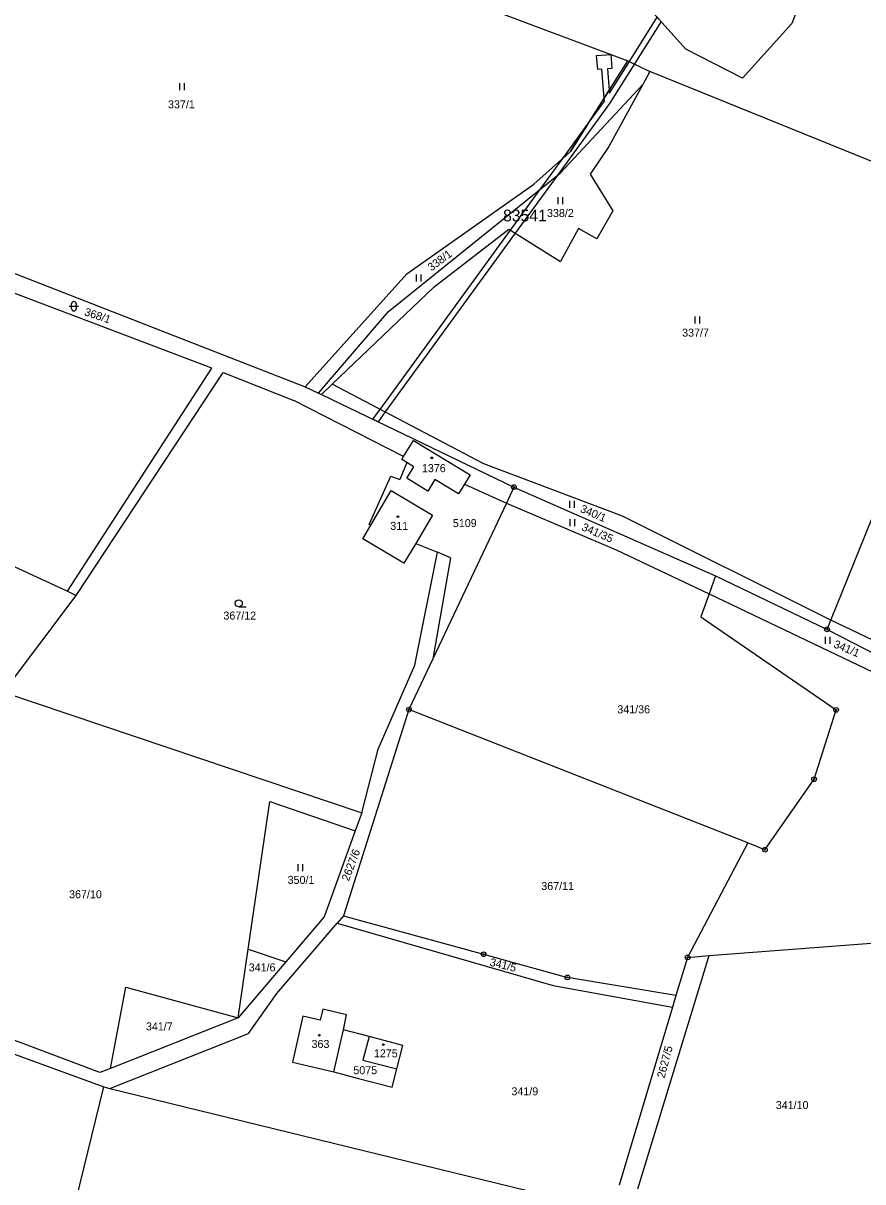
# Model space of a CAD drawing. Extents: x -439246 to -433691, y -1130252 to -1121148.
# Drawn here: x -436804.9 to -436626.4, y -1124037.6 to -1123791.4 of the extents above; entities that cross this region are included whole.
import ezdxf

# ---------------------------------------------------------------- set-up
doc = ezdxf.new("R2010")
doc.units = 0
for name, color, linetype in [('Vrstva 1', 7, 'Continuous'), ('Vrstva 18', 7, 'Continuous'), ('Vrstva 19', 7, 'Continuous'), ('Vrstva 24', 7, 'Continuous'), ('Vrstva 25', 7, 'Continuous'), ('Vrstva 3', 7, 'Continuous'), ('Vrstva 30', 7, 'Continuous'), ('Vrstva 37', 7, 'Continuous'), ('Vrstva 53', 7, 'Continuous'), ('Vrstva 6', 7, 'Continuous')]:
    doc.layers.add(name, color=color, linetype=linetype)

msp = doc.modelspace()

# ---------------------------------------------------------------- linework, layer by layer
at = {"layer": 'Vrstva 1'}
for p, q in [((-436724.05, -1123883.47), (-436747.33, -1123871.55)), ((-436724.05, -1123883.47), (-436721.94, -1123880.01)), ((-436721.94, -1123880.01), (-436709.84, -1123887.31)), ((-436723.36, -1123884.73), (-436724.84, -1123888.36)), ((-436724.43, -1123884.09), (-436724.05, -1123883.47)), ((-436723.36, -1123884.73), (-436724.43, -1123884.09)), ((-436721.86, -1123885.63), (-436723.36, -1123884.73)), ((-436723.35, -1123888.07), (-436721.86, -1123885.63)), ((-436709.84, -1123887.31), (-436711.08, -1123889.35)), ((-436718.89, -1123890.78), (-436723.35, -1123888.07)), ((-436717.37, -1123888.34), (-436718.89, -1123890.78)), ((-436712.33, -1123891.4), (-436717.37, -1123888.34)), ((-436711.08, -1123889.35), (-436712.33, -1123891.4)), ((-436711.08, -1123889.35), (-436702.18, -1123893.33)), ((-436730.97, -1123898.04), (-436726.63, -1123890.68)), ((-436726.63, -1123890.68), (-436717.86, -1123895.93)), ((-436717.86, -1123895.93), (-436721.44, -1123901.9)), ((-436732.66, -1123900.9), (-436730.97, -1123898.04)), ((-436730.97, -1123898.04), (-436731.36, -1123897.88)), ((-436723.95, -1123906.09), (-436732.66, -1123900.9)), ((-436721.44, -1123901.9), (-436723.95, -1123906.09)), ((-436721.44, -1123901.9), (-436716.79, -1123903.78)), ((-436650.87, -1123965.56), (-436722.89, -1123937.23)), ((-436650.87, -1123965.56), (-436663.68, -1123989.86)), ((-436647.23, -1123966.99), (-436650.87, -1123965.56)), ((-436659.11, -1123989.5), (-436618.57, -1123986.35)), ((-436674.24, -1124039.06), (-436659.11, -1123989.5)), ((-436663.68, -1123989.86), (-436666.13, -1123997.99)), ((-436663.68, -1123989.86), (-436659.11, -1123989.5)), ((-436692.21, -1123995.85), (-436666.86, -1124000.45)), ((-436666.13, -1123997.99), (-436689.19, -1123994.12)), ((-436666.13, -1123997.99), (-436666.86, -1124000.45)), ((-436666.86, -1124000.45), (-436678.21, -1124038.28))]:
    msp.add_line(p, q, dxfattribs=at)
for points in [[(-436688.54, -1123818.64), (-436676.38, -1123799.34)], [(-436676.38, -1123799.34), (-436671.7, -1123801.64)], [(-436671.7, -1123801.64), (-436673.19, -1123804.38)], [(-436690.77, -1123823.21), (-436673.19, -1123804.38)], [(-436673.19, -1123804.38), (-436680.39, -1123817.59)], [(-436680.39, -1123817.59), (-436684.36, -1123823.43)], [(-436696.33, -1123825.6), (-436688.54, -1123818.64)], [(-436727.25, -1123852.66), (-436690.77, -1123823.21)], [(-436684.36, -1123823.43), (-436679.57, -1123831.25)], [(-436723.32, -1123844.66), (-436696.33, -1123825.6)], [(-436679.57, -1123831.25), (-436682.92, -1123837.22)], [(-436717.51, -1123847.42), (-436701.65, -1123835.14)], [(-436701.65, -1123835.14), (-436690.65, -1123841.99)], [(-436686.88, -1123834.99), (-436690.65, -1123841.99)], [(-436682.92, -1123837.22), (-436686.88, -1123834.99)], [(-436822.9, -1123838.25), (-436744.96, -1123868.62)], [(-436764.81, -1123864.68), (-436825.31, -1123841.7)], [(-436744.96, -1123868.62), (-436723.32, -1123844.66)], [(-436739.17, -1123868.08), (-436717.51, -1123847.42)], [(-436742.08, -1123870.01), (-436727.25, -1123852.66)], [(-436795.47, -1123912.07), (-436764.81, -1123864.68)], [(-436793.64, -1123912.95), (-436762.35, -1123865.57)], [(-436762.35, -1123865.57), (-436747.33, -1123871.55)], [(-436633.21, -1123918.19), (-436612.33, -1123866.59)], [(-436744.96, -1123868.62), (-436742.08, -1123870.01)], [(-436742.08, -1123870.01), (-436741.49, -1123870.29)], [(-436739.17, -1123868.08), (-436741.49, -1123870.29)], [(-436741.49, -1123870.29), (-436700.57, -1123889.93)], [(-436706.99, -1123884.97), (-436739.17, -1123868.08)], [(-436677.53, -1123896.15), (-436706.99, -1123884.97)], [(-436846.24, -1123888.58), (-436795.47, -1123912.07)], [(-436731.36, -1123897.88), (-436726.71, -1123887.63)], [(-436726.71, -1123887.63), (-436724.84, -1123888.36)], [(-436700.57, -1123889.93), (-436702.18, -1123893.33)], [(-436700.57, -1123889.93), (-436657.71, -1123908.78)], [(-436702.18, -1123893.33), (-436717.78, -1123926.4)], [(-436702.18, -1123893.33), (-436678.86, -1123903.3)], [(-436633.21, -1123918.19), (-436677.53, -1123896.15)], [(-436721.66, -1123927.8), (-436716.79, -1123903.78)], [(-436714.02, -1123904.96), (-436716.79, -1123903.78)], [(-436678.86, -1123903.3), (-436659.1, -1123912.65)], [(-436714.02, -1123904.96), (-436717.78, -1123926.4)], [(-436657.71, -1123908.78), (-436659.1, -1123912.65)], [(-436657.71, -1123908.78), (-436634.02, -1123920.19)], [(-436795.47, -1123912.07), (-436793.64, -1123912.95)], [(-436809.03, -1123933.53), (-436793.64, -1123912.95)], [(-436659.1, -1123912.65), (-436660.85, -1123917.53)], [(-436659.1, -1123912.65), (-436624.26, -1123929.23)], [(-436660.85, -1123917.53), (-436632.1, -1123937.28)], [(-436634.02, -1123920.19), (-436633.21, -1123918.19)], [(-436612.08, -1123928.3), (-436633.21, -1123918.19)], [(-436634.02, -1123920.19), (-436571.37, -1123952.32)], [(-436717.78, -1123926.4), (-436722.89, -1123937.23)], [(-436729.44, -1123945.64), (-436721.66, -1123927.8)], [(-436809.03, -1123933.53), (-436732.89, -1123959.16)], [(-436722.89, -1123937.23), (-436736.79, -1123981.01)], [(-436636.78, -1123952.03), (-436632.1, -1123937.28)], [(-436732.89, -1123959.16), (-436729.44, -1123945.64)], [(-436647.23, -1123966.99), (-436636.78, -1123952.03)], [(-436757.02, -1123988.12), (-436752.43, -1123956.77)], [(-436752.43, -1123956.77), (-436734.28, -1123962.99)], [(-436732.89, -1123959.16), (-436734.28, -1123962.99)], [(-436734.28, -1123962.99), (-436740.88, -1123981.25)], [(-436736.79, -1123981.01), (-436738.17, -1123982.61)], [(-436736.79, -1123981.01), (-436707.01, -1123989.21)], [(-436750.95, -1123997.55), (-436738.17, -1123982.61)], [(-436740.88, -1123981.25), (-436749.03, -1123990.8)], [(-436738.17, -1123982.61), (-436692.21, -1123995.85)], [(-436759.15, -1124002.68), (-436757.02, -1123988.12)], [(-436757.02, -1123988.12), (-436749.03, -1123990.8)], [(-436749.03, -1123990.8), (-436759.15, -1124002.68)], [(-436707.01, -1123989.21), (-436689.19, -1123994.12)], [(-436788.55, -1124014.36), (-436832.84, -1123997.68)], [(-436786.3, -1124013.47), (-436783.06, -1123996.21)], [(-436783.06, -1123996.21), (-436759.15, -1124002.68)], [(-436757, -1124006.03), (-436750.95, -1123997.55)], [(-436833.34, -1124000.72), (-436787.74, -1124017.4)], [(-436759.15, -1124002.68), (-436786.3, -1124013.47)], [(-436745.4, -1124002.39), (-436747.6, -1124012.1)], [(-436741.77, -1124003.2), (-436745.4, -1124002.39)], [(-436741.17, -1124000.89), (-436741.77, -1124003.2)], [(-436736.12, -1124002.04), (-436741.17, -1124000.89)], [(-436736.81, -1124005.28), (-436736.12, -1124002.04)], [(-436738.84, -1124014.16), (-436736.81, -1124005.28)], [(-436731.37, -1124006.69), (-436736.81, -1124005.28)], [(-436786.48, -1124017.71), (-436757, -1124006.03)], [(-436731.37, -1124006.69), (-436732.65, -1124011.68)], [(-436724.16, -1124008.56), (-436731.37, -1124006.69)], [(-436725.43, -1124013.54), (-436724.16, -1124008.56)], [(-436747.6, -1124012.1), (-436738.84, -1124014.16)], [(-436732.65, -1124011.68), (-436725.43, -1124013.54)], [(-436786.3, -1124013.47), (-436788.55, -1124014.36)], [(-436738.84, -1124014.16), (-436733.64, -1124015.61)], [(-436726.42, -1124017.44), (-436725.43, -1124013.54)], [(-436797.92, -1124059.04), (-436787.74, -1124017.4)], [(-436787.74, -1124017.4), (-436786.48, -1124017.71)], [(-436786.48, -1124017.71), (-436678.89, -1124043.98)], [(-436733.64, -1124015.61), (-436726.42, -1124017.44)]]:
    msp.add_lwpolyline(points, dxfattribs=at)
at = {"layer": 'Vrstva 24'}
for centre, radius in [((-436700.57, -1123889.93), 0.5), ((-436700.57, -1123889.93), 0.1), ((-436634.02, -1123920.19), 0.5), ((-436634.02, -1123920.19), 0.1), ((-436722.89, -1123937.23), 0.5), ((-436632.1, -1123937.28), 0.5), ((-436722.89, -1123937.23), 0.1), ((-436632.1, -1123937.28), 0.1), ((-436636.78, -1123952.03), 0.5), ((-436636.78, -1123952.03), 0.1), ((-436647.23, -1123966.99), 0.5), ((-436647.23, -1123966.99), 0.1), ((-436707.01, -1123989.21), 0.5), ((-436707.01, -1123989.21), 0.1), ((-436663.68, -1123989.86), 0.5), ((-436663.68, -1123989.86), 0.1), ((-436689.19, -1123994.12), 0.5), ((-436689.19, -1123994.12), 0.1)]:
    msp.add_circle(centre, radius, dxfattribs=at)
at = {"layer": 'Vrstva 25'}
for p, q in [((-436771.6, -1123805.62), (-436771.6, -1123804.12)), ((-436770.6, -1123805.62), (-436770.6, -1123804.12)), ((-436691.2, -1123829.86), (-436691.2, -1123828.36)), ((-436690.2, -1123829.86), (-436690.2, -1123828.36)), ((-436721.28, -1123846.25), (-436721.28, -1123844.75)), ((-436720.28, -1123846.25), (-436720.28, -1123844.75)), ((-436795.1, -1123851.52), (-436793.1, -1123851.52)), ((-436794.6, -1123852.02), (-436794.6, -1123851.02)), ((-436793.6, -1123851.02), (-436793.6, -1123852.02)), ((-436662.08, -1123855.17), (-436662.08, -1123853.67)), ((-436661.08, -1123855.17), (-436661.08, -1123853.67)), ((-436688.7, -1123894.38), (-436688.7, -1123892.88)), ((-436687.7, -1123894.38), (-436687.7, -1123892.88)), ((-436688.64, -1123898.23), (-436688.64, -1123896.73)), ((-436687.64, -1123898.23), (-436687.64, -1123896.73)), ((-436759.05, -1123915.39), (-436757.45, -1123915.39)), ((-436634.34, -1123923.28), (-436634.34, -1123921.78)), ((-436633.34, -1123923.28), (-436633.34, -1123921.78)), ((-436746.46, -1123971.55), (-436746.46, -1123970.05)), ((-436745.46, -1123971.55), (-436745.46, -1123970.05))]:
    msp.add_line(p, q, dxfattribs=at)
for centre, radius in [((-436718.03, -1123883.73), 0.175), ((-436725.24, -1123896.21), 0.175), ((-436759.05, -1123914.64), 0.75), ((-436741.92, -1124006.41), 0.175), ((-436728.34, -1124008.41), 0.175)]:
    msp.add_circle(centre, radius, dxfattribs=at)
for centre, start, end in [((-436794.1, -1123851.02), 0, 180), ((-436794.1, -1123852.02), 180, 0)]:
    msp.add_arc(centre, 0.5, start, end, dxfattribs=at)
at = {"layer": 'Vrstva 3'}
for points in [[(-436724.05, -1123883.47), (-436721.94, -1123880.01)], [(-436721.94, -1123880.01), (-436709.84, -1123887.31)], [(-436724.43, -1123884.09), (-436724.05, -1123883.47)], [(-436723.36, -1123884.73), (-436724.43, -1123884.09)], [(-436721.86, -1123885.63), (-436723.36, -1123884.73)], [(-436723.35, -1123888.07), (-436721.86, -1123885.63)], [(-436709.84, -1123887.31), (-436711.08, -1123889.35)], [(-436718.89, -1123890.78), (-436723.35, -1123888.07)], [(-436717.37, -1123888.34), (-436718.89, -1123890.78)], [(-436712.33, -1123891.4), (-436717.37, -1123888.34)], [(-436711.08, -1123889.35), (-436712.33, -1123891.4)], [(-436730.97, -1123898.04), (-436726.63, -1123890.68)], [(-436726.63, -1123890.68), (-436717.86, -1123895.93)], [(-436717.86, -1123895.93), (-436721.44, -1123901.9)], [(-436732.66, -1123900.9), (-436730.97, -1123898.04)], [(-436723.95, -1123906.09), (-436732.66, -1123900.9)], [(-436721.44, -1123901.9), (-436723.95, -1123906.09)], [(-436745.4, -1124002.39), (-436747.6, -1124012.1)], [(-436741.77, -1124003.2), (-436745.4, -1124002.39)], [(-436741.17, -1124000.89), (-436741.77, -1124003.2)], [(-436736.12, -1124002.04), (-436741.17, -1124000.89)], [(-436736.81, -1124005.28), (-436736.12, -1124002.04)], [(-436738.84, -1124014.16), (-436736.81, -1124005.28)], [(-436731.37, -1124006.69), (-436732.65, -1124011.68)], [(-436724.16, -1124008.56), (-436731.37, -1124006.69)], [(-436725.43, -1124013.54), (-436724.16, -1124008.56)], [(-436747.6, -1124012.1), (-436738.84, -1124014.16)], [(-436732.65, -1124011.68), (-436725.43, -1124013.54)]]:
    msp.add_lwpolyline(points, dxfattribs=at)
at = {"layer": 'Vrstva 30'}
for points in [[(-436680.27, -1123806.26), (-436676.04, -1123799.51), (-436670.13, -1123790.08), (-436669.3, -1123791.02), (-436674.96, -1123800.04), (-436680.23, -1123808.45), (-436691.26, -1123823.61), (-436700.28, -1123835.99), (-436727.93, -1123873.98), (-436729.45, -1123876.07), (-436730.55, -1123875.54), (-436729, -1123873.42), (-436701.3, -1123835.36), (-436694.85, -1123826.5), (-436690.21, -1123820.14), (-436688.54, -1123818.64), (-436684.77, -1123812.66), (-436681.34, -1123807.95), (-436681.39, -1123807.3), (-436680.32, -1123805.6), (-436680.27, -1123806.26)], [(-436681.88, -1123801.14), (-436682.77, -1123801.2), (-436683.01, -1123798.21), (-436680.01, -1123798), (-436679.78, -1123800.99), (-436680.68, -1123801.04), (-436680.32, -1123805.6), (-436681.39, -1123807.3), (-436681.88, -1123801.14)], [(-436690.21, -1123820.14), (-436684.77, -1123812.66), (-436688.54, -1123818.64), (-436690.21, -1123820.14)]]:
    msp.add_lwpolyline(points, dxfattribs=at)
at = {"layer": 'Vrstva 37'}
for centre in [(-436718.03, -1123883.73), (-436725.24, -1123896.21), (-436741.92, -1124006.41), (-436728.34, -1124008.41)]:
    msp.add_circle(centre, 0.175, dxfattribs=at)
at = {"layer": 'Vrstva 6'}
for points in [[(-436793.98, -1123755.28), (-436676.38, -1123799.34)], [(-436634.76, -1123774.02), (-436641.53, -1123791.42)], [(-436664.06, -1123796.9), (-436675.41, -1123784.15)], [(-436641.53, -1123791.42), (-436652, -1123803.08)], [(-436652, -1123803.08), (-436664.06, -1123796.9)], [(-436598.1, -1123831.44), (-436671.7, -1123801.64)]]:
    msp.add_lwpolyline(points, dxfattribs=at)

# ---------------------------------------------------------------- texts
at = {"layer": 'Vrstva 18'}
for s, p in [('337/1', (-436774.09, -1123809.46)), ('338/2', (-436693.54, -1123832.56)), ('337/7', (-436664.82, -1123857.97)), ('5109', (-436713.55, -1123898.44)), ('367/12', (-436762.31, -1123918.09)), ('341/36', (-436678.6, -1123938.01)), ('350/1', (-436748.66, -1123974.25)), ('367/10', (-436795.11, -1123977.3)), ('367/11', (-436694.76, -1123975.55)), ('341/6', (-436756.94, -1123992.84)), ('341/7', (-436778.78, -1124005.38)), ('5075', (-436734.7, -1124014.69)), ('341/9', (-436701.1, -1124019.17)), ('341/10', (-436644.92, -1124022.09))]:
    msp.add_text(s, height=1.7, dxfattribs=at).set_placement(p)
for s, rotation, p in [('338/1', 36.7126, (-436718.12, -1123844.15)), ('368/1', 341.3645, (-436792, -1123853.4)), ('340/1', 336.7418, (-436686.64, -1123895.16)), ('341/35', 336.7418, (-436686.33, -1123899.05)), ('341/1', 337.4451, (-436632.79, -1123923.93)), ('2627/6', 69.391, (-436735.66, -1123973.79)), ('341/5', 346.356, (-436705.83, -1123991.62)), ('2627/5', 75.2218, (-436668.57, -1124015.64))]:
    msp.add_text(s, height=1.7, rotation=rotation, dxfattribs=at).set_placement(p)
at = {"layer": 'Vrstva 19'}
for s, p in [('1376', (-436720.13, -1123886.77)), ('311', (-436726.85, -1123899.03)), ('363', (-436743.58, -1124009.11)), ('1275', (-436730.33, -1124011.11))]:
    msp.add_text(s, height=1.7, dxfattribs=at).set_placement(p)
at = {"layer": 'Vrstva 53'}
msp.add_text('83541', height=2.5, dxfattribs=at).set_placement((-436702.88, -1123833.49))

doc.saveas('drawing.dxf')
